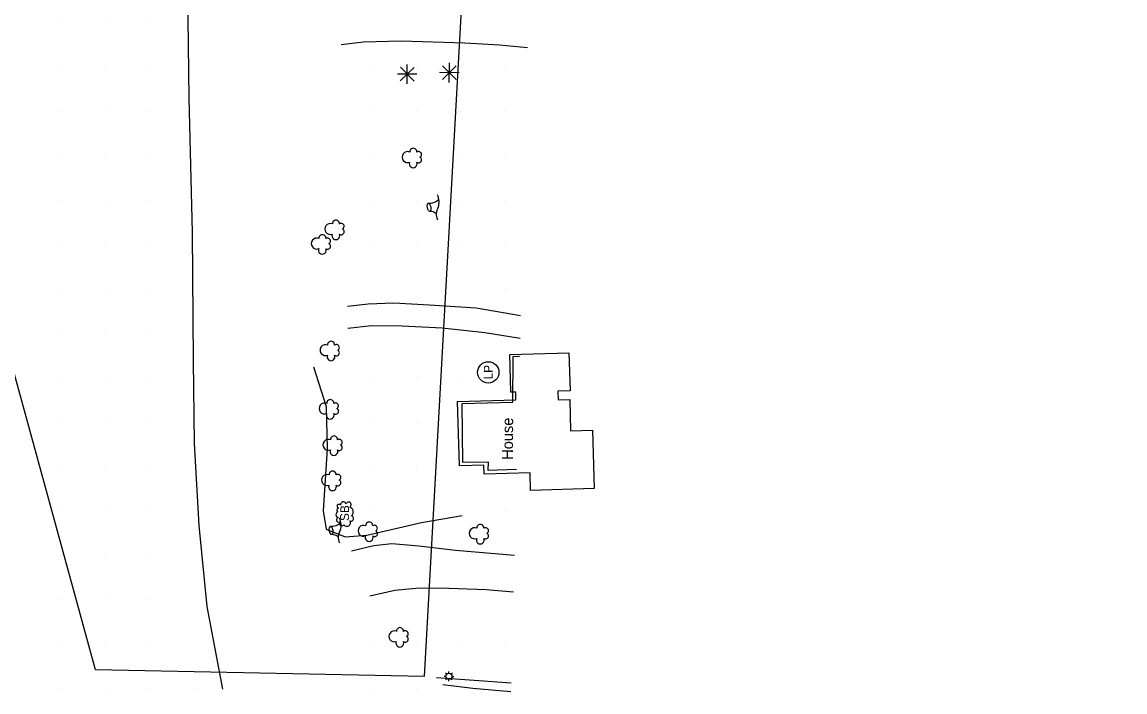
# Model space of a CAD drawing. Extents: x 19528164 to 19545171, y 7585743 to 7602745.
# Drawn here: x 19538887.4 to 19539384.5, y 7590688.4 to 7590990.4 of the extents above; entities that cross this region are included whole.
import ezdxf

# ---------------------------------------------------------------- set-up
doc = ezdxf.new("R2010")
doc.units = 0
for name, color, linetype in [('PhoBreakLine', 7, 'Continuous'), ('PhoBuilding', 7, 'Continuous'), ('PhoISAEPoints', 7, 'Continuous'), ('PhoNotesDesign', 7, 'Continuous'), ('PhoSurveyLimits', 7, 'Continuous'), ('PhoVegetation', 7, 'Continuous'), ('SurNaturalCells', 7, 'Continuous'), ('SurROWRail', 7, 'Continuous')]:
    doc.layers.add(name, color=color, linetype=linetype)

msp = doc.modelspace()

# ---------------------------------------------------------------- linework, layer by layer
at = {"layer": 'PhoBreakLine'}
for points in [[(19538977.84, 7590689.62), (19538970.79, 7590726.93), (19538967.2, 7590763.47), (19538965.07, 7590800.31), (19538964.71, 7590837.65), (19538964.26, 7590895.44), (19538962.68, 7590956), (19538961.54, 7591052.07), (19538960.98, 7591129.76)], [(19539110.33, 7590788.63), (19539097.5, 7590788.28), (19539097.69, 7590791.9), (19539086.08, 7590791.75), (19539085.72, 7590818.41), (19539108.68, 7590819.01), (19539108.84, 7590839.59), (19539111.66, 7590839.71)], [(19539018.7, 7590834.93), (19539024.52, 7590817.04), (19539024.97, 7590798.03), (19539023.12, 7590769.97), (19539024.52, 7590761.8), (19539033.09, 7590758.35), (19539042.87, 7590759.02), (19539067.48, 7590764.76), (19539085.74, 7590767.98)], [(19539074.26, 7590694.94), (19539091.14, 7590693.7), (19539107.82, 7590692.47)], [(19539107.71, 7590688.38), (19539090.57, 7590689.96), (19539077.01, 7590691.57)]]:
    msp.add_lwpolyline(points, dxfattribs=at)
at = {"layer": 'PhoBuilding'}
msp.add_lwpolyline([(19539083.69, 7590819.37), (19539110.03, 7590820.11), (19539109.93, 7590823.58), (19539107.7, 7590823.52), (19539107.22, 7590840.46), (19539133.92, 7590841.22), (19539134.41, 7590824.07), (19539128.96, 7590823.92), (19539129.07, 7590820.09), (19539134.26, 7590820.24), (19539134.66, 7590806.14), (19539144.55, 7590806.42), (19539145.3, 7590780.07), (19539116.6, 7590779.25), (19539116.38, 7590787.11), (19539095.73, 7590786.52), (19539095.62, 7590790.6), (19539084.52, 7590790.28)], close=True, dxfattribs=at)
at = {"layer": 'PhoISAEPoints'}
for p, q in [((19538905, 7590990), (19538905, 7590990)), ((19538925, 7590990), (19538925, 7590990)), ((19538945, 7590990), (19538945, 7590990)), ((19538905, 7590970), (19538905, 7590970)), ((19538925, 7590970), (19538925, 7590970)), ((19538945, 7590970), (19538945, 7590970)), ((19539045, 7590970), (19539045, 7590970)), ((19539065, 7590970), (19539065, 7590970)), ((19539085, 7590970), (19539085, 7590970)), ((19539105, 7590970), (19539105, 7590970)), ((19538905, 7590950), (19538905, 7590950)), ((19538925, 7590950), (19538925, 7590950)), ((19538945, 7590950), (19538945, 7590950)), ((19539045, 7590950), (19539045, 7590950)), ((19539065, 7590950), (19539065, 7590950)), ((19539085, 7590950), (19539085, 7590950)), ((19539105, 7590950), (19539105, 7590950)), ((19538905, 7590930), (19538905, 7590930)), ((19538925, 7590930), (19538925, 7590930)), ((19538945, 7590930), (19538945, 7590930)), ((19539045, 7590930), (19539045, 7590930)), ((19539065, 7590930), (19539065, 7590930)), ((19539085, 7590930), (19539085, 7590930)), ((19539105, 7590930), (19539105, 7590930)), ((19538905, 7590910), (19538905, 7590910)), ((19538925, 7590910), (19538925, 7590910)), ((19538945, 7590910), (19538945, 7590910)), ((19539045, 7590910), (19539045, 7590910)), ((19539065, 7590910), (19539065, 7590910)), ((19539085, 7590910), (19539085, 7590910)), ((19539105, 7590910), (19539105, 7590910)), ((19538905, 7590890), (19538905, 7590890)), ((19538925, 7590890), (19538925, 7590890)), ((19538945, 7590890), (19538945, 7590890)), ((19539025, 7590890), (19539025, 7590890)), ((19539045, 7590890), (19539045, 7590890)), ((19539065, 7590890), (19539065, 7590890)), ((19539085, 7590890), (19539085, 7590890)), ((19539105, 7590890), (19539105, 7590890)), ((19538905, 7590870), (19538905, 7590870)), ((19538925, 7590870), (19538925, 7590870)), ((19538945, 7590870), (19538945, 7590870)), ((19539105, 7590870), (19539105, 7590870)), ((19538905, 7590850), (19538905, 7590850)), ((19538925, 7590850), (19538925, 7590850)), ((19538945, 7590850), (19538945, 7590850)), ((19538905, 7590830), (19538905, 7590830)), ((19538925, 7590830), (19538925, 7590830)), ((19538945, 7590830), (19538945, 7590830)), ((19539045, 7590830), (19539045, 7590830)), ((19539065, 7590830), (19539065, 7590830)), ((19539085, 7590830), (19539085, 7590830)), ((19538905, 7590810), (19538905, 7590810)), ((19538925, 7590810), (19538925, 7590810)), ((19538945, 7590810), (19538945, 7590810)), ((19539045, 7590810), (19539045, 7590810)), ((19539065, 7590810), (19539065, 7590810)), ((19538905, 7590790), (19538905, 7590790)), ((19538925, 7590790), (19538925, 7590790)), ((19538945, 7590790), (19538945, 7590790)), ((19539045, 7590790), (19539045, 7590790)), ((19539065, 7590790), (19539065, 7590790)), ((19538905, 7590770), (19538905, 7590770)), ((19538925, 7590770), (19538925, 7590770)), ((19538945, 7590770), (19538945, 7590770)), ((19539045, 7590770), (19539045, 7590770)), ((19539105, 7590770), (19539105, 7590770)), ((19538905, 7590750), (19538905, 7590750)), ((19538925, 7590750), (19538925, 7590750)), ((19538945, 7590750), (19538945, 7590750)), ((19538905, 7590730), (19538905, 7590730)), ((19538925, 7590730), (19538925, 7590730)), ((19538945, 7590730), (19538945, 7590730)), ((19538905, 7590710), (19538905, 7590710)), ((19538925, 7590710), (19538925, 7590710)), ((19538945, 7590710), (19538945, 7590710)), ((19539045, 7590710), (19539045, 7590710)), ((19539065, 7590710), (19539065, 7590710)), ((19539085, 7590710), (19539085, 7590710)), ((19539105, 7590710), (19539105, 7590710)), ((19538905, 7590690), (19538905, 7590690)), ((19538925, 7590690), (19538925, 7590690)), ((19538945, 7590690), (19538945, 7590690)), ((19538965, 7590690), (19538965, 7590690)), ((19539045, 7590690), (19539045, 7590690)), ((19539065, 7590690), (19539065, 7590690))]:
    msp.add_line(p, q, dxfattribs=at)
at = {"layer": 'PhoSurveyLimits'}
msp.add_lwpolyline([(19543262.35, 7595683.22), (19543257.95, 7595379.65), (19542419.97, 7595255.07), (19541879.23, 7595109.17), (19539317.07, 7592404.33), (19539317.07, 7592404.33), (19539199.99, 7591704.87), (19539183.97, 7591336.2), (19539095.01, 7591334.37), (19539095.54, 7591180.74), (19539068.71, 7590695.4), (19538920.46, 7590698.41), (19538798.64, 7591142.79), (19538688.52, 7591615.61), (19537853.91, 7591634.47), (19537374.94, 7591324.13)], dxfattribs=at)
at = {"layer": 'PhoVegetation'}
for p, q in [((19539079.99, 7590963.17), (19539080.04, 7590971.92)), ((19539065.38, 7590966.86), (19539056.63, 7590966.91)), ((19539064.12, 7590969.96), (19539057.9, 7590963.81)), ((19539064.08, 7590963.78), (19539057.93, 7590970)), ((19539060.98, 7590962.51), (19539061.03, 7590971.26)), ((19539061.01, 7590966.89), (19539061.01, 7590966.89)), ((19539084.39, 7590967.52), (19539075.64, 7590967.57)), ((19539083.13, 7590970.62), (19539076.91, 7590964.47)), ((19539083.09, 7590964.44), (19539076.94, 7590970.66)), ((19539080.02, 7590967.55), (19539080.02, 7590967.55))]:
    msp.add_line(p, q, dxfattribs=at)
for centre, radius, start, end in [((19539061.21, 7590929.5), 2.46, 67.8949, 291.4847), ((19539063.73, 7590931.88), 1.6, 355.688, 183.6916), ((19539066.1, 7590930.67), 1.34, 296.214, 125.0932), ((19539063.7, 7590926.47), 1.76, 155.1722, 24.2074), ((19539066.12, 7590928.25), 1.34, 232.44, 65.0122), ((19539068.07, 7590909.26), 7.33, 340.884, 26.1238), ((19539071.02, 7590914.79), 6.05, 265.1674, 314.959), ((19539080.19, 7590903.66), 6.1, 148.3637, 203.3878), ((19539071.35, 7590900.8), 4.21, 49.1734, 91.5139), ((19539026.33, 7590897.07), 2.46, 67.8949, 291.4847), ((19539028.86, 7590899.45), 1.6, 355.688, 183.6916), ((19539031.25, 7590895.83), 1.34, 232.44, 65.0122), ((19539031.23, 7590898.24), 1.34, 296.214, 125.0932), ((19539020.22, 7590890.51), 2.46, 67.8949, 291.4847), ((19539022.74, 7590892.9), 1.6, 355.688, 183.6916), ((19539025.11, 7590891.68), 1.34, 296.214, 125.0932), ((19539028.83, 7590894.04), 1.76, 155.1722, 24.2074), ((19539022.71, 7590887.49), 1.76, 155.1722, 24.2074), ((19539025.13, 7590889.27), 1.34, 232.44, 65.0122), ((19539024.18, 7590842.48), 2.46, 67.8949, 291.4847), ((19539026.71, 7590844.87), 1.6, 355.688, 183.6916), ((19539029.1, 7590841.24), 1.34, 232.44, 65.0122), ((19539029.08, 7590843.65), 1.34, 296.214, 125.0932), ((19539026.68, 7590839.46), 1.76, 155.1722, 24.2074), ((19539023.79, 7590816.16), 2.46, 67.8949, 291.4847), ((19539026.31, 7590818.55), 1.6, 355.688, 183.6916), ((19539028.68, 7590817.33), 1.34, 296.214, 125.0932), ((19539026.28, 7590813.14), 1.76, 155.1722, 24.2074), ((19539028.7, 7590814.92), 1.34, 232.44, 65.0122), ((19539028.01, 7590802.17), 1.6, 355.688, 183.6916), ((19539025.48, 7590799.78), 2.46, 67.8949, 291.4847), ((19539027.98, 7590796.76), 1.76, 155.1722, 24.2074), ((19539030.4, 7590798.54), 1.34, 232.44, 65.0122), ((19539030.38, 7590800.95), 1.34, 296.214, 125.0932), ((19539027.37, 7590786.31), 1.6, 355.688, 183.6916), ((19539024.84, 7590783.93), 2.46, 67.8949, 291.4847), ((19539029.76, 7590782.68), 1.34, 232.44, 65.0122), ((19539029.74, 7590785.1), 1.34, 296.214, 125.0932), ((19539027.34, 7590780.9), 1.76, 155.1722, 24.2074), ((19539030.28, 7590772.07), 0.9, 41.0834, 256.1012), ((19539032.25, 7590772.75), 1.3, 20.5937, 184.0585), ((19539034.6, 7590772.79), 1.21, 294.5192, 159.5769), ((19539030.3, 7590768.36), 1.41, 112.2935, 255.4734), ((19539030.06, 7590770.4), 0.794, 90.1503, 248.4737), ((19539034.45, 7590769.52), 2.27, 309.7081, 73.3875), ((19539035.68, 7590766.61), 1.18, 246.7156, 79.4501), ((19539026.85, 7590769.09), 6.05, 265.1674, 314.959), ((19539030.14, 7590765.98), 1.04, 100.2846, 304.051), ((19539031.49, 7590764.35), 1.09, 135.0353, 326.4972), ((19539023.91, 7590763.56), 7.33, 340.884, 26.1238), ((19539033.76, 7590764.72), 1.67, 215.5187, 28.9747), ((19539041.35, 7590761), 2.46, 67.8949, 291.4847), ((19539043.87, 7590763.39), 1.6, 355.688, 183.6916), ((19539046.24, 7590762.17), 1.34, 296.214, 125.0932), ((19539093.96, 7590762.31), 1.6, 355.688, 183.6916), ((19539027.19, 7590755.1), 4.21, 49.1734, 91.5139), ((19539036.03, 7590757.96), 6.1, 148.3637, 203.3878), ((19539043.84, 7590757.97), 1.76, 155.1722, 24.2074), ((19539046.26, 7590759.76), 1.34, 232.44, 65.0122), ((19539091.43, 7590759.92), 2.46, 67.8949, 291.4847), ((19539093.93, 7590756.89), 1.76, 155.1722, 24.2074), ((19539096.35, 7590758.68), 1.34, 232.44, 65.0122), ((19539096.33, 7590761.09), 1.34, 296.214, 125.0932), ((19539055.21, 7590713.43), 2.46, 67.8949, 291.4847), ((19539057.73, 7590715.81), 1.6, 355.688, 183.6916), ((19539060.12, 7590712.18), 1.34, 232.44, 65.0122), ((19539060.1, 7590714.6), 1.34, 296.214, 125.0932), ((19539057.7, 7590710.4), 1.76, 155.1722, 24.2074)]:
    msp.add_arc(centre, radius, start, end, dxfattribs=at)
for centre in [(19539070.87, 7590906.88), (19539026.71, 7590761.18)]:
    msp.add_ellipse(centre, major_axis=(0.36, -1.88), ratio=0.385758, dxfattribs=at)
at = {"layer": 'SurNaturalCells'}
for p, q in [((19539077.65, 7590695.44), (19539078.46, 7590695.43)), ((19539078.27, 7590693.89), (19539078.85, 7590694.47)), ((19539078.86, 7590696.39), (19539078.29, 7590696.97)), ((19539079.81, 7590693.25), (19539079.81, 7590694.06)), ((19539079.83, 7590696.78), (19539079.83, 7590697.6)), ((19539081.35, 7590693.88), (19539080.78, 7590694.46)), ((19539080.79, 7590696.38), (19539081.37, 7590696.95)), ((19539081.18, 7590695.42), (19539081.99, 7590695.41))]:
    msp.add_line(p, q, dxfattribs=at)
for centre, radius in [((19539097.55, 7590832.44), 4.8), ((19539079.82, 7590695.42), 1.36)]:
    msp.add_circle(centre, radius, dxfattribs=at)
at = {"layer": 'SurROWRail'}
for points in [[(19539031.31, 7590980.33), (19539041.31, 7590981.47), (19539058.32, 7590981.84), (19539086.98, 7590980.96), (19539102.66, 7590980.16), (19539115.3, 7590978.89)], [(19539112.14, 7590858.01), (19539092.07, 7590861.35), (19539070.91, 7590862.78), (19539054.96, 7590863.67), (19539043.4, 7590863.18), (19539034.05, 7590862.08)], [(19539034.28, 7590852.43), (19539044.96, 7590853.52), (19539058.78, 7590853.36), (19539076.76, 7590852.46), (19539096.01, 7590850.44), (19539111.88, 7590847.93)], [(19539109.32, 7590749.96), (19539082.76, 7590752.21), (19539066.27, 7590754.13), (19539054.07, 7590755.13), (19539046.03, 7590754.24), (19539035.84, 7590751.87)], [(19539044.12, 7590731.75), (19539055.4, 7590734.2), (19539066.42, 7590735.29), (19539079.77, 7590735.13), (19539096.57, 7590734.53), (19539108.89, 7590733.48)]]:
    msp.add_lwpolyline(points, dxfattribs=at)

# ---------------------------------------------------------------- texts
at = {"layer": 'PhoNotesDesign'}
msp.add_text('House', height=4.92, rotation=89.6898, dxfattribs=at).set_placement((19539108.65, 7590793.02))
at = {"layer": 'PhoVegetation'}
msp.add_text('SB', height=3.999, rotation=89.6898, dxfattribs=at).set_placement((19539034.79, 7590765.43))
at = {"layer": 'SurNaturalCells'}
msp.add_text('LP', height=3.999, rotation=89.6898, dxfattribs=at).set_placement((19539099.53, 7590829.25))

doc.saveas('drawing.dxf')
